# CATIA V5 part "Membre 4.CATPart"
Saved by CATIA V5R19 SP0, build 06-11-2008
Part number: Membre 4
Bounding box of the stored display mesh (mm): x -5 to 5, y -14.997 to 14.997, z -15 to 265
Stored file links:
  D:\thinkmotion-MPB\CIAO82010_JCF\PLANTECOSTE\0593\assemblage 593\Membre 4.CATPart
  D:\thinkmotion-MPB\CIAO82010_JCF\PLANTECOSTE\0593\assemblage 593\593-Plantecoste.CATProduct
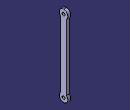
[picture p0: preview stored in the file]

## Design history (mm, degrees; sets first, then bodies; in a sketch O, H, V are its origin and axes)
External parameters (linked from other documents)
  `External.Diamètre axe` = 10 mm
  External.Longueur.1 = 300 mm
Body1 (main body)
  Sketch1 on yz-plane, origin (0, 0, 0), H (0, 1, 0), V (0, 0, 1)
    circle A1 centre (0, 0) radius 5
    axis line L1 (0, 0) -> (0, 133.3077)
    point P1 (0, 0)
    arc A2 centre (0, 0) radius 15 from (0, -15) to (10, 11.1803) ccw
    point P3 (0, -15)
    point P4 (10, 11.1803)
    line L2 (10, 11.1803) -> (10, 238.8197)
    point P5 (10, 238.8197)
    arc A3 centre (0, 250) radius 15 from (10, 238.8197) to (0, 265) ccw
    point P6 (0, 250)
    point P7 (0, 265)
    point P8 (10, 238.8197)
    circle A4 centre (0, 250) radius 5
    point P9 (-10, 11.1803)
    point P10 (0, -15)
    arc A5 centre (0, 0) radius 15 from (0, -15) to (-10, 11.1803) cw
    point P12 (-10, 238.8197)
    line L3 (-10, 11.1803) -> (-10, 238.8197)
    point P13 (0, 265)
    point P14 (-10, 238.8197)
    arc A6 centre (0, 250) radius 15 from (-10, 238.8197) to (0, 265) cw
    radius A1 = 5 {= `External.Diamètre axe` /2}
    radius A2 = 15 {= `External.Diamètre axe` *1.5}
    radius A4 = 5 {= `External.Diamètre axe` /2}
    radius A3 = 15 {= `External.Diamètre axe` *1.5}
    distance L2 L1 = 10 {= `External.Diamètre axe`}
    distance P6 H = 250 {= External.Longueur.1 /1.2}
    coincidence: P1 H, P1 V, P3 V, P6 L1, P7 L1, P8 P5, P3 P10, P7 P13, P12 P14
    vertical: L1 V, L2 V
    symmetry: P4 P9 L1, P3 P10 L1, A2 A5 L1, P5 P12 L1, L2 L3 L1, P7 P13 L1, P8 P14 L1, A3 A6 L1
  Pad1: profile Sketch1, direction (1, 0, 0), length 5, opposite side length 5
